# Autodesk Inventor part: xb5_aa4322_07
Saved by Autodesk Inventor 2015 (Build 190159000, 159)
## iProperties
Created: 2018-05
Part Number: xb5_aa4322_07
Checked By: TraceParts S.A.
Material: Generic
Catalog Web Link: www.traceparts.com
Document SubType Name: Modeling
Designer: TraceParts
Density: 1 g/cm^3
Appearance: Default
Company: TraceParts S.A.
Author: TraceParts
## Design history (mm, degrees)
feature "xb5_aa4322_07.ipt"
body "Solid1"
